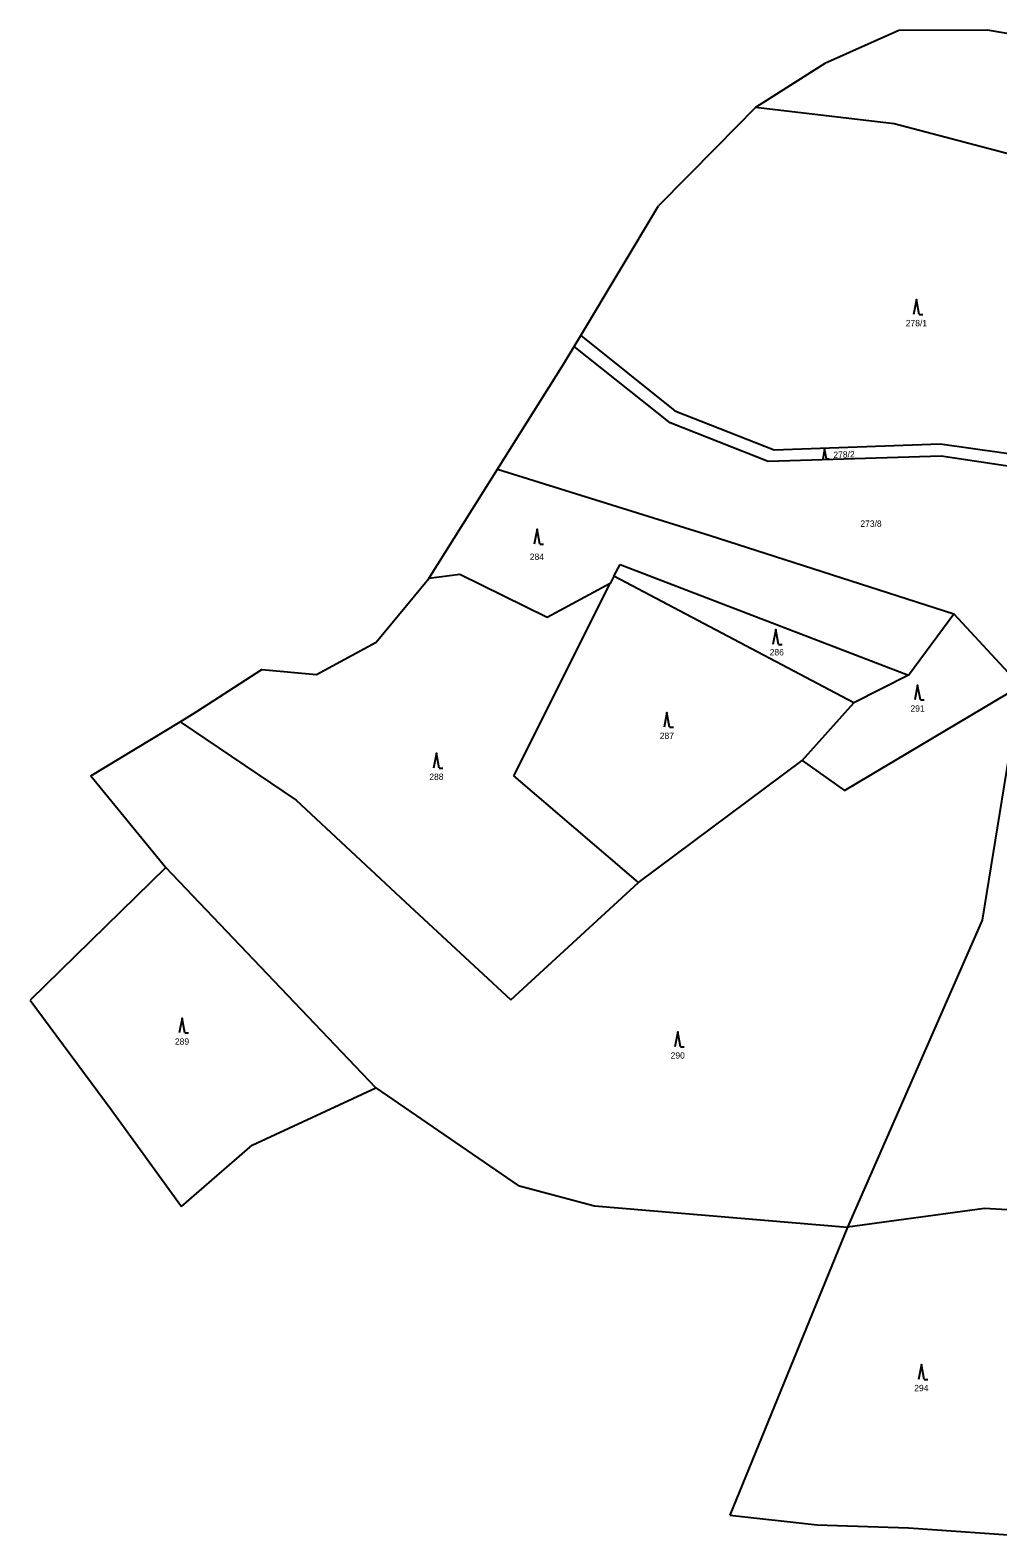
# Model space of a CAD drawing. Extents: x -791548 to -789311, y -1142631 to -1140855.
# Drawn here: x -791547.5 to -791288.6, y -1141792.5 to -1141389 of the extents above; entities that cross this region are included whole.
import ezdxf
from ezdxf.enums import TextEntityAlignment as Align

# ---------------------------------------------------------------- set-up
doc = ezdxf.new("R2010")
doc.units = 0
doc.header["$LTSCALE"] = 0.68
doc.layers.add('1', color=7, linetype='Continuous', lineweight=25)
doc.layers.add('3', color=7, linetype='Continuous', lineweight=25)
doc.layers.add('2', color=7, linetype='Continuous')

msp = doc.modelspace()

# ---------------------------------------------------------------- linework, layer by layer
at = {"layer": '1'}
for p, q in [((-791315.11, -1141389.12), (-791334.89, -1141397.97)), ((-791291.36, -1141389.04), (-791315.11, -1141389.12)), ((-791279.89, -1141391.04), (-791291.36, -1141389.04)), ((-791334.89, -1141397.97), (-791353.44, -1141409.76)), ((-791353.44, -1141409.76), (-791363.96, -1141420.42)), ((-791316.37, -1141414.15), (-791353.44, -1141409.76)), ((-791253.36, -1141430.65), (-791316.37, -1141414.15)), ((-791363.96, -1141420.42), (-791379.37, -1141436.05)), ((-791400.17, -1141470.75), (-791379.37, -1141436.05)), ((-791401.91, -1141473.66), (-791400.17, -1141470.75)), ((-791400.17, -1141470.75), (-791375.03, -1141490.95)), ((-791404.79, -1141478.46), (-791401.91, -1141473.66)), ((-791376.27, -1141494.11), (-791401.91, -1141473.66)), ((-791422.45, -1141506.56), (-791404.79, -1141478.46)), ((-791375.03, -1141490.95), (-791348.48, -1141501.34)), ((-791350.02, -1141504.46), (-791376.27, -1141494.11)), ((-791348.48, -1141501.34), (-791304.05, -1141499.75)), ((-791304.05, -1141499.75), (-791251.2, -1141507.28)), ((-791303.73, -1141503.05), (-791350.02, -1141504.46)), ((-791253.04, -1141510.74), (-791303.73, -1141503.05)), ((-791440.82, -1141535.82), (-791422.45, -1141506.56)), ((-791422.45, -1141506.56), (-791365.54, -1141524.27)), ((-791365.54, -1141524.27), (-791300.37, -1141545.28)), ((-791391.34, -1141535.14), (-791389.68, -1141532.01)), ((-791389.68, -1141532.01), (-791312.5, -1141561.68)), ((-791454.92, -1141552.8), (-791440.82, -1141535.82)), ((-791432.54, -1141534.75), (-791440.82, -1141535.82)), ((-791409.2, -1141546.21), (-791432.54, -1141534.75)), ((-791418.07, -1141588.64), (-791392.35, -1141537.16)), ((-791392.35, -1141537.16), (-791409.2, -1141546.21)), ((-791391.34, -1141535.14), (-791392.35, -1141537.16)), ((-791327.15, -1141569.05), (-791391.34, -1141535.14)), ((-791312.5, -1141561.68), (-791300.37, -1141545.28)), ((-791300.37, -1141545.28), (-791282.55, -1141564.55)), ((-791470.91, -1141561.44), (-791454.92, -1141552.8)), ((-791502.91, -1141571.41), (-791485.51, -1141560.17)), ((-791485.51, -1141560.17), (-791470.91, -1141561.44)), ((-791312.5, -1141561.68), (-791327.15, -1141569.05)), ((-791329.63, -1141592.51), (-791282.55, -1141564.55)), ((-791340.91, -1141584.5), (-791327.15, -1141569.05)), ((-791507.37, -1141574.12), (-791502.91, -1141571.41)), ((-791531.25, -1141588.6), (-791507.37, -1141574.12)), ((-791507.37, -1141574.12), (-791476.36, -1141595.07)), ((-791384.75, -1141617.13), (-791340.91, -1141584.5)), ((-791340.91, -1141584.5), (-791329.63, -1141592.51)), ((-791285.82, -1141584.43), (-791292.76, -1141627.2)), ((-791531.25, -1141588.6), (-791511.21, -1141613.12)), ((-791384.75, -1141617.13), (-791418.07, -1141588.64)), ((-791476.36, -1141595.07), (-791447.19, -1141622.31)), ((-791511.21, -1141613.12), (-791547.51, -1141648.68)), ((-791455.01, -1141672.14), (-791511.21, -1141613.12)), ((-791418.9, -1141648.58), (-791384.75, -1141617.13)), ((-791447.19, -1141622.31), (-791418.9, -1141648.58)), ((-791292.76, -1141627.2), (-791328.81, -1141709.42)), ((-791547.51, -1141648.68), (-791525.8, -1141677.94)), ((-791488.13, -1141687.47), (-791455.01, -1141672.14)), ((-791455.01, -1141672.14), (-791416.9, -1141698.25)), ((-791525.8, -1141677.94), (-791506.99, -1141703.85)), ((-791506.99, -1141703.85), (-791488.13, -1141687.47)), ((-791416.9, -1141698.25), (-791396.47, -1141703.69)), ((-791396.47, -1141703.69), (-791328.81, -1141709.42)), ((-791292.15, -1141704.35), (-791328.81, -1141709.42)), ((-791328.81, -1141709.42), (-791360.34, -1141786.44)), ((-791360.34, -1141786.44), (-791336.97, -1141789.08)), ((-791336.97, -1141789.08), (-791312.52, -1141789.87)), ((-791312.52, -1141789.87), (-791274.7, -1141792.53))]:
    msp.add_line(p, q, dxfattribs=at)
msp.add_lwpolyline([(-791274.49, -1141752.52), (-791270.89, -1141705.66), (-791292.15, -1141704.35)], dxfattribs=at)
at = {"layer": '3'}
for p, q in [((-791309.62, -1141465.15), (-791308.624, -1141465.15)), ((-791334.428, -1141503.79), (-791333.76, -1141503.79)), ((-791411.11, -1141526.59), (-791410.114, -1141526.59)), ((-791347.27, -1141553.46), (-791346.274, -1141553.46)), ((-791309.32, -1141568.3), (-791308.324, -1141568.3)), ((-791376.4, -1141575.61), (-791375.404, -1141575.61)), ((-791438.06, -1141586.57), (-791437.064, -1141586.57)), ((-791506.13, -1141657.41), (-791505.134, -1141657.41)), ((-791373.49, -1141661.15), (-791372.494, -1141661.15)), ((-791308.31, -1141750.16), (-791307.314, -1141750.16))]:
    msp.add_line(p, q, dxfattribs=at)
for points in [[(-791309.62, -1141465.15), (-791310.37, -1141461.15), (-791311.12, -1141465.15)], [(-791334.428, -1141503.79), (-791334.93, -1141501.11), (-791335.432, -1141503.79)], [(-791411.11, -1141526.59), (-791411.86, -1141522.59), (-791412.61, -1141526.59)], [(-791347.27, -1141553.46), (-791348.02, -1141549.46), (-791348.77, -1141553.46)], [(-791309.32, -1141568.3), (-791310.07, -1141564.3), (-791310.82, -1141568.3)], [(-791376.4, -1141575.61), (-791377.15, -1141571.61), (-791377.9, -1141575.61)], [(-791438.06, -1141586.57), (-791438.81, -1141582.57), (-791439.56, -1141586.57)], [(-791506.13, -1141657.41), (-791506.88, -1141653.41), (-791507.63, -1141657.41)], [(-791373.49, -1141661.15), (-791374.24, -1141657.15), (-791374.99, -1141661.15)], [(-791308.31, -1141750.16), (-791309.06, -1141746.16), (-791309.81, -1141750.16)]]:
    msp.add_lwpolyline(points, dxfattribs=at)

# ---------------------------------------------------------------- texts
at = {"layer": '2'}
for s, p in [('278/1', (-791310.37, -1141468.282)), ('273/8', (-791322.52, -1141521.962)), ('284', (-791411.919, -1141530.822)), ('286', (-791347.739, -1141556.382)), ('291', (-791310.069, -1141571.432)), ('287', (-791377.149, -1141578.742)), ('288', (-791438.809, -1141589.702)), ('289', (-791506.879, -1141660.542)), ('290', (-791374.239, -1141664.282)), ('294', (-791309.059, -1141753.292))]:
    msp.add_text(s, height=1.7, dxfattribs=at).set_placement(p, align=Align.CENTER)
msp.add_text('278/2', height=1.7, rotation=2, dxfattribs=at).set_placement((-791329.7097, -1141503.4605), align=Align.CENTER)

doc.saveas('drawing.dxf')
